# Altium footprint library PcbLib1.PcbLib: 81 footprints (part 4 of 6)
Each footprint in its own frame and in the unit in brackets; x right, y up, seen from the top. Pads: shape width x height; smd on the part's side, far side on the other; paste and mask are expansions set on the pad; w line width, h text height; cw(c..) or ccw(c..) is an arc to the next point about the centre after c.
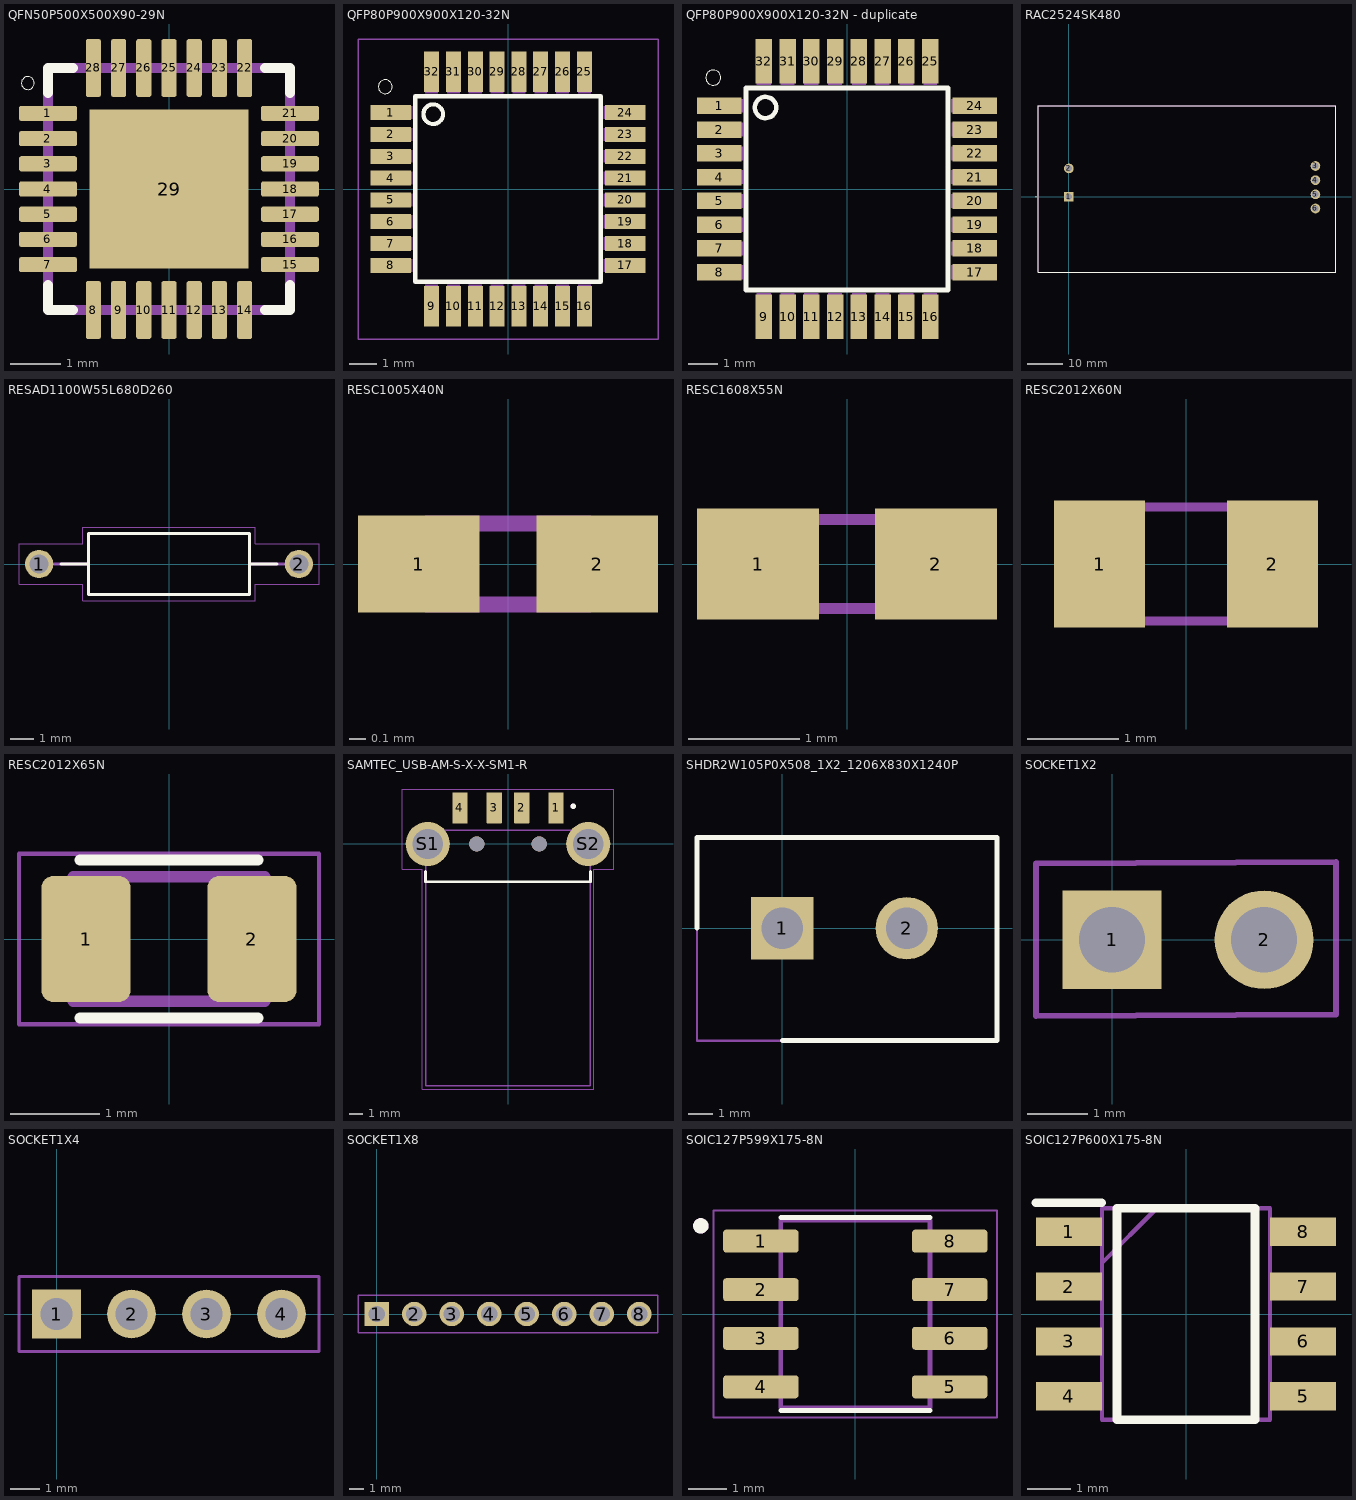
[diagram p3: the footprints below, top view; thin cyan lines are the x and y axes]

## QFN50P500X500X90-29N [mm]
pads (29):
  rrect30% 1.15x0.3 smd mask-0.01: 1(-2.4,1.5) 2(-2.4,1) 3(-2.4,0.5) 4(-2.4,0) 5(-2.4,-0.5) 6(-2.4,-1) 7(-2.4,-1.5) 15(2.4,-1.5) 16(2.4,-1) 17(2.4,-0.5) 18(2.4,0) 19(2.4,0.5) 20(2.4,1) 21(2.4,1.5)
  rrect30% 0.3x1.15 smd mask-0.01: 8(-1.5,-2.4) 9(-1,-2.4) 10(-0.5,-2.4) 11(0,-2.4) 12(0.5,-2.4) 13(1,-2.4) 14(1.5,-2.4) 22(1.5,2.4) 23(1,2.4) 24(0.5,2.4) 25(0,2.4) 26(-0.5,2.4) 27(-1,2.4) 28(-1.5,2.4)
  rect 3.15x3.15 smd paste-3: 29(0,0)
Top Overlay:
  circle w0: c-2.8,2.1 r0.127
  lines w0.203: -2.398,-1.902 -2.398,-2.398 -1.902,-2.398 ; -2.398,1.902 -2.398,2.398 -1.902,2.398 ; 1.902,-2.398 2.398,-2.398 2.398,-1.902 ; 1.902,2.398 2.398,2.398 2.398,1.902
Top Paste:
  region: 1,-1.002 -1.002,-1.002 -1.002,1 1,1
Mechanical 13:
  lines w0.203: -2.4,-1.9 -2.4,1.9 ; -1.9,-2.4 1.9,-2.4 ; -1.9,2.4 1.9,2.4 ; 2.4,-1.9 2.4,1.9
3D body "A4988SETTR-T.STEP": height 1, standoff 0, extent -2.425,-2.5 2.575,2.5

## QFP80P900X900X120-32N [mm]
pads (32):
  rect 1.5x0.55 smd: 1(-4.3,2.8) 2(-4.3,2) 3(-4.3,1.2) 4(-4.3,0.4) 5(-4.3,-0.4) 6(-4.3,-1.2) 7(-4.3,-2) 8(-4.3,-2.8) 17(4.3,-2.8) 18(4.3,-2) 19(4.3,-1.2) 20(4.3,-0.4) 21(4.3,0.4) 22(4.3,1.2) 23(4.3,2) 24(4.3,2.8)
  rect 0.55x1.5 smd: 9(-2.8,-4.3) 10(-2,-4.3) 11(-1.2,-4.3) 12(-0.4,-4.3) 13(0.4,-4.3) 14(1.2,-4.3) 15(2,-4.3) 16(2.8,-4.3) 25(2.8,4.3) 26(2,4.3) 27(1.2,4.3) 28(0.4,4.3) 29(-0.4,4.3) 30(-1.2,4.3) 31(-2,4.3) 32(-2.8,4.3)
Top Overlay:
  circle w0: c-4.5,3.75 r0.254
  circle w0.152: c-2.743,2.743 r0.359
  lines w0.152: -3.4,-3.4 -3.4,3.4 3.4,3.4 3.4,-3.4 -3.4,-3.4
Mechanical 13:
  region: -2.571,3.511 -3.033,3.511 -3.033,4.497 -2.571,4.497
  region: -1.771,3.512 -2.232,3.512 -2.232,4.497 -1.771,4.497
  region: -0.971,3.513 -1.432,3.513 -1.432,4.497 -0.971,4.497
  region: -0.171,3.517 -0.631,3.517 -0.631,4.497 -0.171,4.497
  region: 0.629,3.513 0.172,3.513 0.172,4.497 0.629,4.497
  region: 1.429,3.513 0.973,3.513 0.973,4.497 1.429,4.497
  region: 2.229,3.513 1.775,3.513 1.775,4.497 2.229,4.497
  region: 3.029,3.514 2.577,3.514 2.577,4.497 3.029,4.497
  region: 4.497,2.578 3.514,2.578 3.514,3.029 4.497,3.029
  region: 4.497,1.778 3.519,1.778 3.519,2.229 4.497,2.229
  region: 4.497,0.973 3.513,0.973 3.513,1.429 4.497,1.429
  region: 4.497,0.172 3.51,0.172 3.51,0.629 4.497,0.629
  region: 4.497,-0.629 3.511,-0.629 3.511,-0.171 4.497,-0.171
  region: 4.497,-1.432 3.513,-1.432 3.513,-0.971 4.497,-0.971
  region: 4.497,-2.232 3.512,-2.232 3.512,-1.771 4.497,-1.771
  region: 4.497,-3.031 3.509,-3.031 3.509,-2.571 4.497,-2.571
  region: 3.029,-4.505 2.576,-4.505 2.576,-3.506 3.029,-3.506
  region: 2.229,-4.506 1.775,-4.506 1.775,-3.506 2.229,-3.506
  region: 1.429,-4.505 0.973,-4.505 0.973,-3.506 1.429,-3.506
  region: 0.629,-4.505 0.172,-4.505 0.172,-3.506 0.629,-3.506
  region: -0.171,-4.509 -0.63,-4.509 -0.63,-3.506 -0.171,-3.506
  region: -0.971,-4.507 -1.432,-4.507 -1.432,-3.506 -0.971,-3.506
  region: -1.771,-4.5 -2.23,-4.5 -2.23,-3.506 -1.771,-3.506
  region: -2.571,-4.506 -3.035,-4.506 -3.035,-3.506 -2.571,-3.506
  region: -3.506,-3.036 -4.507,-3.036 -4.507,-2.571 -3.506,-2.571
  region: -3.506,-2.232 -4.503,-2.232 -4.503,-1.771 -3.506,-1.771
  region: -3.506,-1.432 -4.507,-1.432 -4.507,-0.971 -3.506,-0.971
  region: -3.506,-0.629 -4.503,-0.629 -4.503,-0.171 -3.506,-0.171
  region: -3.506,0.172 -4.5,0.172 -4.5,0.629 -3.506,0.629
  region: -3.506,0.975 -4.511,0.975 -4.511,1.429 -3.506,1.429
  region: -3.506,1.775 -4.505,1.775 -4.505,2.229 -3.506,2.229
  region: -3.506,2.577 -4.507,2.577 -4.507,3.029 -3.506,3.029
Mechanical 15:
  lines w0.05: -5.5,-5.5 -5.5,5.5 5.5,5.5 5.5,-5.5 -5.5,-5.5
3D body "ATMEGA328P-AU--3DModel-STEP-56544.STEP": height 0.53, standoff -0.67, extent -4.5,-4.5 4.5,4.5

## QFP80P900X900X120-32N - duplicate [mm]
pads (32):
  rect 1.5x0.55 smd: 1(-4.3,2.8) 2(-4.3,2) 3(-4.3,1.2) 4(-4.3,0.4) 5(-4.3,-0.4) 6(-4.3,-1.2) 7(-4.3,-2) 8(-4.3,-2.8) 17(4.3,-2.8) 18(4.3,-2) 19(4.3,-1.2) 20(4.3,-0.4) 21(4.3,0.4) 22(4.3,1.2) 23(4.3,2) 24(4.3,2.8)
  rect 0.55x1.5 smd: 9(-2.8,-4.3) 10(-2,-4.3) 11(-1.2,-4.3) 12(-0.4,-4.3) 13(0.4,-4.3) 14(1.2,-4.3) 15(2,-4.3) 16(2.8,-4.3) 25(2.8,4.3) 26(2,4.3) 27(1.2,4.3) 28(0.4,4.3) 29(-0.4,4.3) 30(-1.2,4.3) 31(-2,4.3) 32(-2.8,4.3)
Top Overlay:
  circle w0: c-4.5,3.75 r0.254
  circle w0.152: c-2.743,2.743 r0.359
  lines w0.152: -3.4,-3.4 -3.4,3.4 3.4,3.4 3.4,-3.4 -3.4,-3.4
Mechanical 13:
  region: -2.571,3.511 -3.033,3.511 -3.033,4.497 -2.571,4.497
  region: -1.771,3.512 -2.232,3.512 -2.232,4.497 -1.771,4.497
  region: -0.971,3.513 -1.432,3.513 -1.432,4.497 -0.971,4.497
  region: -0.171,3.517 -0.631,3.517 -0.631,4.497 -0.171,4.497
  region: 0.629,3.513 0.172,3.513 0.172,4.497 0.629,4.497
  region: 1.429,3.513 0.973,3.513 0.973,4.497 1.429,4.497
  region: 2.229,3.513 1.775,3.513 1.775,4.497 2.229,4.497
  region: 3.029,3.514 2.577,3.514 2.577,4.497 3.029,4.497
  region: 4.497,2.578 3.514,2.578 3.514,3.029 4.497,3.029
  region: 4.497,1.778 3.519,1.778 3.519,2.229 4.497,2.229
  region: 4.497,0.973 3.513,0.973 3.513,1.429 4.497,1.429
  region: 4.497,0.172 3.51,0.172 3.51,0.629 4.497,0.629
  region: 4.497,-0.629 3.511,-0.629 3.511,-0.171 4.497,-0.171
  region: 4.497,-1.432 3.513,-1.432 3.513,-0.971 4.497,-0.971
  region: 4.497,-2.232 3.512,-2.232 3.512,-1.771 4.497,-1.771
  region: 4.497,-3.031 3.509,-3.031 3.509,-2.571 4.497,-2.571
  region: 3.029,-4.505 2.576,-4.505 2.576,-3.506 3.029,-3.506
  region: 2.229,-4.506 1.775,-4.506 1.775,-3.506 2.229,-3.506
  region: 1.429,-4.505 0.973,-4.505 0.973,-3.506 1.429,-3.506
  region: 0.629,-4.505 0.172,-4.505 0.172,-3.506 0.629,-3.506
  region: -0.171,-4.509 -0.63,-4.509 -0.63,-3.506 -0.171,-3.506
  region: -0.971,-4.507 -1.432,-4.507 -1.432,-3.506 -0.971,-3.506
  region: -1.771,-4.5 -2.23,-4.5 -2.23,-3.506 -1.771,-3.506
  region: -2.571,-4.506 -3.035,-4.506 -3.035,-3.506 -2.571,-3.506
  region: -3.506,-3.036 -4.507,-3.036 -4.507,-2.571 -3.506,-2.571
  region: -3.506,-2.232 -4.503,-2.232 -4.503,-1.771 -3.506,-1.771
  region: -3.506,-1.432 -4.507,-1.432 -4.507,-0.971 -3.506,-0.971
  region: -3.506,-0.629 -4.503,-0.629 -4.503,-0.171 -3.506,-0.171
  region: -3.506,0.172 -4.5,0.172 -4.5,0.629 -3.506,0.629
  region: -3.506,0.975 -4.511,0.975 -4.511,1.429 -3.506,1.429
  region: -3.506,1.775 -4.505,1.775 -4.505,2.229 -3.506,2.229
  region: -3.506,2.577 -4.507,2.577 -4.507,3.029 -3.506,3.029
3D body "ATMEGA328P-AU--3DModel-STEP-56544.STEP": height 0.53, standoff -0.67, extent -4.5,-4.5 4.5,4.5

## RAC2524SK480 [mm]
pads (6):
  rect 2.7x2.7 hole 1.8: 1(0,0)
  round 2.7 hole 1.8: 2(0,7.92) 3(68.9,8.61) 4(68.9,4.65) 5(68.9,0.69) 6(68.9,-3.27)
Top Overlay:
  lines w0.1: -9.2,0 cw(c-9.15,0) -9.1,0 cw(c-9.15,0) -9.2,0
  lines w0.2: -8.58,-21.043 -8.58,25.387 74.65,25.387 74.65,-21.043 -8.58,-21.043
Mechanical 13:
  lines w0.1: -8.58,-21.04 -8.58,25.39 74.65,25.39 74.65,-21.04 -8.58,-21.04
3D body "RAC25-24SK_480.stp": height 31.09, standoff -3.31, extent -8.586,-21.044 74.649,25.391

## RESAD1100W55L680D260 [mm]
height 2.6
pads (2):
  round 1.2 hole 0.8: 1(-5.5,0) 2(5.5,0)
Top Overlay:
  lines w0.127: -4.58,0 -3.4,0 ; 4.58,0 3.4,0 ; -3.4,0 -3.4,1.3 3.4,1.3 3.4,0 ; -3.4,0 -3.4,-1.3 3.4,-1.3 3.4,0
Mechanical 13:
  lines w0.127: -4.9,0 -3.4,0 ; 4.9,0 3.4,0 ; -3.4,0 -3.4,1.3 3.4,1.3 3.4,0 ; -3.4,0 -3.4,-1.3 3.4,-1.3 3.4,0
Mechanical 15:
  lines w0.05: -6.35,-0.85 -3.65,-0.85 -3.65,-1.55 3.65,-1.55 3.65,-0.85 6.35,-0.85 6.35,0.85 3.65,0.85 3.65,1.55 -3.65,1.55 -3.65,0.85 -6.35,0.85 -6.35,-0.85
3D body "step_temp.STEP": height 2.6, standoff -25.53, extent -5.775,-1.3 5.775,1.3

## RESC1005X40N [mm]
pads (2):
  rect 0.75x0.6 smd: 1(-0.55,0) 2(0.55,0)
Mechanical 13:
  lines w0.1: -0.5,-0.25 -0.5,0.25 0.5,0.25 0.5,-0.25 -0.5,-0.25
3D body "CRCW04022K00FKEE.stp": height 0.4, standoff 0, extent -0.5,-0.25 0.5,0.25

## RESC1608X55N [mm]
pads (2):
  rect 1.1x1 smd: 1(-0.8,0) 2(0.8,0)
Mechanical 13:
  lines w0.1: -0.8,-0.4 0.8,-0.4 0.8,0.4 -0.8,0.4 -0.8,-0.4
3D body "RC0603FR-072KL.stp": height 0.55, standoff 0, extent -0.8,-0.4 0.8,0.4

## RESC2012X60N [mm]
pads (2):
  rect 1x1.4 smd: 1(-0.95,0) 2(0.95,0)
Mechanical 13:
  lines w0.1: -1,-0.625 -1,0.625 1,0.625 1,-0.625 -1,-0.625
3D body "CHP0805-FX-1002ELF.stp": height 0.6, standoff 0, extent -1,-0.625 1,0.625

## RESC2012X65N [mm]
pads (2):
  rrect25% 1x1.42 smd: 1(-0.935,0) 2(0.935,0)
Top Overlay:
  lines w0.127: -1,-0.89 1,-0.89 ; -1,0.89 1,0.89
Mechanical 13:
  lines w0.127: -1.08,-0.7 1.08,-0.7 1.08,0.7 -1.08,0.7 -1.08,-0.7
Mechanical 15:
  lines w0.05: -1.69,-0.96 1.69,-0.96 1.69,0.96 -1.69,0.96 -1.69,-0.96
3D body "step_temp.STEP": height 0.6, standoff 0, extent -1,-0.625 1,0.625

## SAMTEC_USB-AM-S-X-X-SM1-R [mm]
pads (8):
  rrect4% 1.1x2.25 smd: 1(3.5,2.625) 2(1,2.625) 3(-1,2.625) 4(-3.5,2.625)
  round 3.216 hole 2.2: S1(-5.85,0) S2(5.85,0)
  round 1.1 hole 1.1 unplated: ""(-2.275,0) ""(2.275,0)
Top Overlay:
  circle w0.2: c4.75,2.75 r0.1
  lines w0.2: -6,-2 -6,-2.75 6,-2.75 6,-2
Mechanical 13:
  circle w0.2: c4.75,2.75 r0.1
  lines w0.1: -6,-2.75 6,-2.75 ; -6,-17.6 -6,1 6,1 6,-17.6 -6,-17.6
  text "PCB EDGE" at -3.5,-2.5 h1.02
Mechanical 15:
  lines w0.05: -7.71,-1.86 -7.71,4 7.71,4 7.71,-1.86 6.25,-1.86 6.25,-17.85 -6.25,-17.85 -6.25,-1.86 -7.71,-1.86
3D body "USB-A-S-F-B-TH.stp": height 7.47, standoff -4.42, extent -7.874,-10.6 7.874,3.5

## SHDR2W105P0X508_1X2_1206X830X1240P [mm]
pads (2):
  rect 2.55x2.55 hole 1.7: 1(0,0)
  round 2.55 hole 1.7: 2(5.08,0)
Top Overlay:
  lines w0.2: -3.49,0 -3.49,3.71 8.77,3.71 8.77,-4.59 0,-4.59
Mechanical 13:
  lines w0.1: -3.49,-4.59 -3.49,3.71 8.77,3.71 8.77,-4.59 -3.49,-4.59
3D body "WJ2EDGVC-5.08-2P.stp": height 12.4, standoff -4.2, extent -3.49,-4.15 8.57,4.15

## SOCKET1X2 [mm]
pads (2):
  rect 1.65x1.65 hole 1.1: 1(0,0)
  round 1.65 hole 1.1: 2(2.54,0)
Mechanical 13:
  lines w0.1: -1.27,-1.27 3.74,-1.245 3.74,1.295 -1.27,1.27 -1.27,-1.27
3D body "929850-01-02-30.stp": height 8.26, standoff -3.43, extent -1.27,-1.27 3.81,1.27
3D body "929850-01-02-30.stp": height 8.26, standoff -3.43, extent 3.81,-1.27 8.89,1.27

## SOCKET1X4 [mm]
pads (4):
  rect 1.65x1.65 hole 1.1: 1(0,0)
  round 1.65 hole 1.1: 2(2.54,0) 3(5.08,0) 4(7.62,0)
Mechanical 13:
  lines w0.1: -1.27,-1.27 8.89,-1.27 8.89,1.27 -1.27,1.27 -1.27,-1.27
3D body "929850-01-02-30.stp": height 8.26, standoff -3.43, extent -1.27,-1.27 3.81,1.27
3D body "929850-01-02-30.stp": height 8.26, standoff -3.43, extent 3.81,-1.27 8.89,1.27

## SOCKET1X8 [mm]
pads (8):
  rect 1.65x1.65 hole 1.1: 1(0,0)
  round 1.65 hole 1.1: 2(2.54,0) 3(5.08,0) 4(7.62,0) 5(10.16,0) 6(12.7,0) 7(15.24,0) 8(17.78,0)
Mechanical 13:
  lines w0.1: -1.27,-1.27 -1.27,1.27 19.05,1.27 19.05,-1.27 -1.27,-1.27
3D body "929850-01-02-30.stp": height 8.26, standoff -3.43, extent -1.27,-1.27 3.81,1.27
3D body "929850-01-02-30.stp": height 8.26, standoff -3.43, extent 3.81,-1.27 8.89,1.27
3D body "929850-01-02-30.stp": height 8.26, standoff -3.43, extent 8.89,-1.27 13.97,1.27
3D body "929850-01-02-30.stp": height 8.26, standoff -3.43, extent 13.97,-1.27 19.05,1.27

## SOIC127P599X175-8N [mm]
pads (8):
  rrect25% 1.97x0.6 smd: 1(-2.47,1.905) 2(-2.47,0.635) 3(-2.47,-0.635) 4(-2.47,-1.905) 5(2.47,-1.905) 6(2.47,-0.635) 7(2.47,0.635) 8(2.47,1.905)
Top Overlay:
  circle w0.2: c-4.04,2.305 r0.1
  lines w0.127: -1.95,-2.525 1.95,-2.525 ; -1.95,2.525 1.95,2.525
Mechanical 13:
  circle w0.2: c-4.04,2.305 r0.1
  lines w0.127: -1.95,-2.452 1.95,-2.452 1.95,2.452 -1.95,2.452 -1.95,-2.452
Mechanical 15:
  lines w0.05: -3.705,-2.702 3.705,-2.702 3.705,2.702 -3.705,2.702 -3.705,-2.702
3D body "step_temp.STEP": height 1.75, standoff 0, extent -2.997,-2.451 2.997,2.451

## SOIC127P600X175-8N [mm]
pads (8):
  rect 1.528x0.65 smd: 1(-2.711,1.905) 2(-2.711,0.635) 3(-2.711,-0.635) 4(-2.711,-1.905) 5(2.711,-1.905) 6(2.711,-0.635) 7(2.711,0.635) 8(2.711,1.905)
Top Overlay:
  lines w0.2: -3.475,2.58 -1.948,2.58 ; -1.598,-2.452 -1.598,2.452 1.598,2.452 1.598,-2.452 -1.598,-2.452
Mechanical 13:
  lines w0.1: -1.948,1.182 -0.678,2.452 ; -1.948,-2.452 -1.948,2.452 1.948,2.452 1.948,-2.452 -1.948,-2.452
3D body "OPA350UA_2K5.stp": height 1.75, standoff 0, extent -2.997,-2.452 2.997,2.452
